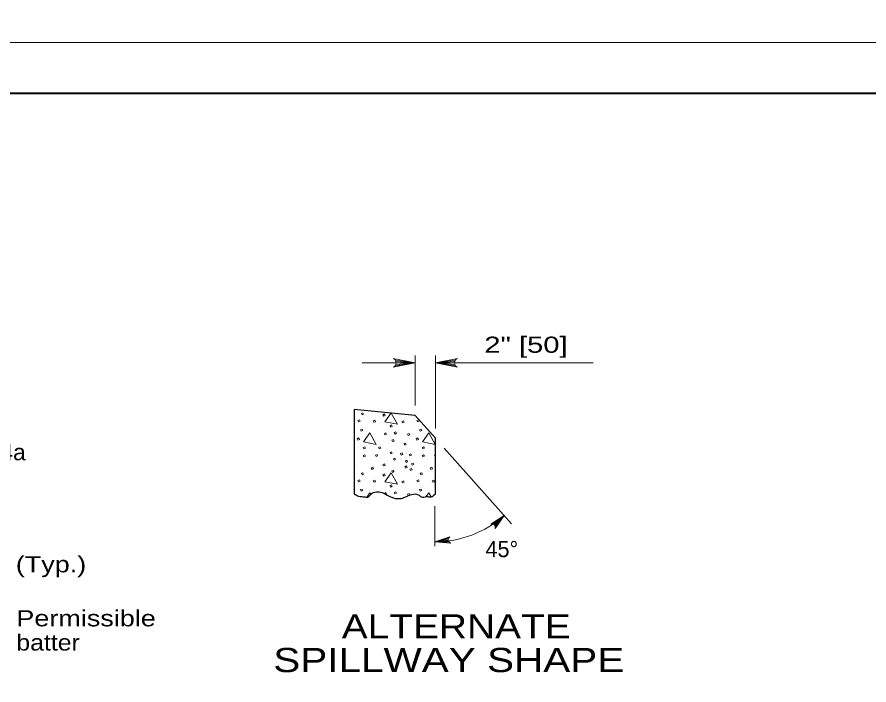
# Model space of a CAD drawing. Extents: x -1431.2 to -1397.2, y -1045.1 to -1001.1.
# Drawn here: x -1419.2 to -1410.82, y -1029.4 to -1022.83 of the extents above; entities that cross this region are included whole.
import ezdxf
from ezdxf.enums import TextEntityAlignment as Align

# ---------------------------------------------------------------- set-up
doc = ezdxf.new("R2010")
doc.units = 0
doc.header["$LTSCALE"] = 0.064
doc.linetypes.add('LONG_DASHED', pattern=[7.5, 6, -1.5])
doc.layers.add('1', color=7, linetype='Continuous', lineweight=13)
doc.layers.add('7', color=7, linetype='Continuous', lineweight=13)

msp = doc.modelspace()

# ---------------------------------------------------------------- linework, layer by layer
at = {"layer": '1', "lineweight": 25}
for p, q in [((-1429.24575, -1023.57983), (-1397.74575, -1023.57983)), ((-1415.08442, -1026.97317), (-1415.28442, -1026.74817)), ((-1415.08442, -1027.52167), (-1415.08442, -1026.97317))]:
    msp.add_line(p, q, dxfattribs=at)
at = {"layer": '1'}
for p, q in [((-1415.28442, -1026.65283), (-1415.28442, -1026.16033)), ((-1415.08442, -1026.87775), (-1415.08442, -1026.16033)), ((-1415.283, -1026.23167), (-1415.80542, -1026.23167)), ((-1415.481, -1026.26192), (-1415.283, -1026.23167)), ((-1415.47867, -1026.20433), (-1415.283, -1026.23167)), ((-1415.47358, -1026.23167), (-1415.283, -1026.23167)), ((-1415.4735, -1026.24925), (-1415.283, -1026.23167)), ((-1415.47208, -1026.21783), (-1415.283, -1026.23167)), ((-1415.47, -1026.23167), (-1415.283, -1026.23167)), ((-1414.88733, -1026.20433), (-1415.083, -1026.23167)), ((-1414.89392, -1026.21783), (-1415.083, -1026.23167)), ((-1413.53358, -1026.23167), (-1415.083, -1026.23167)), ((-1414.89592, -1026.23167), (-1415.083, -1026.23167)), ((-1414.8925, -1026.24925), (-1415.083, -1026.23167)), ((-1414.885, -1026.26192), (-1415.083, -1026.23167)), ((-1414.33558, -1027.81517), (-1414.997, -1027.07142)), ((-1415.88217, -1027.21875), (-1415.88375, -1027.21933)), ((-1415.75667, -1027.55067), (-1415.72858, -1027.51058)), ((-1415.72858, -1027.51058), (-1415.72058, -1027.525)), ((-1415.17508, -1027.548), (-1415.14883, -1027.51058)), ((-1415.14883, -1027.51058), (-1415.12708, -1027.5495)), ((-1415.08908, -1027.64242), (-1415.08908, -1028.03642)), ((-1414.52175, -1027.81608), (-1414.409, -1027.73458)), ((-1414.51183, -1027.82008), (-1414.409, -1027.73458)), ((-1414.50367, -1027.82617), (-1414.409, -1027.73458)), ((-1414.49717, -1027.83675), (-1414.409, -1027.73458)), ((-1414.495, -1027.8465), (-1414.409, -1027.73458)), ((-1414.9525, -1027.95417), (-1415.08892, -1027.991)), ((-1414.95642, -1027.96325), (-1415.08892, -1027.991)), ((-1414.9575, -1027.97633), (-1415.08892, -1027.991)), ((-1414.95517, -1027.98558), (-1415.08892, -1027.991)), ((-1414.9495, -1027.99458), (-1415.08892, -1027.991))]:
    msp.add_line(p, q, dxfattribs=at)
at = {"layer": '1', "linetype": 'LONG_DASHED'}
for points in [[(-1431.24575, -1023.07983), (-1397.24575, -1023.07983), (-1397.24575, -1001.07983), (-1431.24575, -1001.07983)], [(-1431.24575, -1045.07983), (-1397.24575, -1045.07983), (-1397.24575, -1023.07983), (-1431.24575, -1023.07983)]]:
    msp.add_lwpolyline(points, close=True, dxfattribs=at)
at = {"layer": '1', "lineweight": 40}
msp.add_lwpolyline([(-1429.24575, -1023.57983), (-1397.74575, -1023.57983), (-1397.74575, -1044.57983), (-1429.24575, -1044.57983)], close=True, dxfattribs=at)
at = {"layer": '1'}
for points in [[(-1415.49917, -1026.27492), (-1415.283, -1026.23167), (-1415.49917, -1026.1885)], [(-1414.86683, -1026.27492), (-1415.083, -1026.23167), (-1414.86683, -1026.1885)], [(-1415.51808, -1026.72542), (-1415.456, -1026.83633), (-1415.58108, -1026.81192), (-1415.52017, -1026.72508)], [(-1415.08442, -1027.13592), (-1415.09392, -1027.14042), (-1415.08783, -1027.15467), (-1415.08442, -1027.153)], [(-1415.88375, -1027.236), (-1415.87608, -1027.233), (-1415.88217, -1027.21875)], [(-1415.57092, -1027.50858), (-1415.58617, -1027.51567), (-1415.58417, -1027.52033)], [(-1415.57125, -1027.52633), (-1415.56483, -1027.52383), (-1415.57092, -1027.50858)], [(-1414.49742, -1027.86208), (-1414.409, -1027.73458), (-1414.54017, -1027.81808)], [(-1414.94058, -1027.9435), (-1415.08892, -1027.991), (-1414.93383, -1028.00425)]]:
    msp.add_lwpolyline(points, dxfattribs=at)
at = {"layer": '1', "lineweight": 25}
msp.add_lwpolyline([(-1415.28442, -1026.74817), (-1415.88375, -1026.68958), (-1415.88375, -1027.52167)], dxfattribs=at)
at = {"layer": '1'}
for points in [[(-1415.79675, -1026.7225), (-1415.812, -1026.72858), (-1415.80592, -1026.74283), (-1415.79058, -1026.73667)], [(-1415.58417, -1026.73467), (-1415.59942, -1026.74175), (-1415.59233, -1026.756), (-1415.57708, -1026.74992)], [(-1415.83133, -1026.79267), (-1415.84658, -1026.79875), (-1415.83942, -1026.813), (-1415.82417, -1026.80683)], [(-1415.67975, -1026.79667), (-1415.695, -1026.80283), (-1415.68892, -1026.817), (-1415.67367, -1026.81092)], [(-1415.39908, -1026.80283), (-1415.41433, -1026.80892), (-1415.40717, -1026.82317), (-1415.39192, -1026.817)], [(-1415.25158, -1026.79267), (-1415.26683, -1026.79875), (-1415.25975, -1026.813), (-1415.2445, -1026.80683)], [(-1415.80383, -1026.88317), (-1415.81908, -1026.88925), (-1415.813, -1026.9035), (-1415.79775, -1026.89742)], [(-1415.57092, -1026.91875), (-1415.58617, -1026.92583), (-1415.58008, -1026.94008), (-1415.56483, -1026.934)], [(-1415.515, -1026.8425), (-1415.53025, -1026.84858), (-1415.52417, -1026.86383), (-1415.50892, -1026.85667)], [(-1415.47333, -1026.91058), (-1415.48858, -1026.91667), (-1415.4825, -1026.93192), (-1415.46717, -1026.92483)], [(-1415.22417, -1026.88317), (-1415.23942, -1026.88925), (-1415.23325, -1026.9035), (-1415.218, -1026.89742)], [(-1415.83742, -1026.97058), (-1415.85267, -1026.97775), (-1415.84558, -1026.99192), (-1415.83025, -1026.98583)], [(-1415.72858, -1026.92075), (-1415.6655, -1027.03367), (-1415.79058, -1027.00925)], [(-1415.49667, -1026.98683), (-1415.51192, -1026.993), (-1415.50483, -1027.00717), (-1415.48958, -1027.00108)], [(-1415.34208, -1026.92583), (-1415.35733, -1026.933), (-1415.35125, -1026.94725), (-1415.336, -1026.94008)], [(-1415.25767, -1026.97058), (-1415.27292, -1026.97775), (-1415.26583, -1026.99192), (-1415.25058, -1026.98583)], [(-1415.14883, -1026.92075), (-1415.08583, -1027.03367), (-1415.21092, -1027.00925)], [(-1415.77942, -1027.057), (-1415.79467, -1027.06317), (-1415.78758, -1027.07733), (-1415.77233, -1027.07125)], [(-1415.62792, -1027.057), (-1415.64317, -1027.06417), (-1415.63708, -1027.07842), (-1415.62175, -1027.07225)], [(-1415.37667, -1027.02042), (-1415.39192, -1027.0265), (-1415.38583, -1027.04175), (-1415.37058, -1027.03467)], [(-1415.19975, -1027.057), (-1415.215, -1027.06317), (-1415.20783, -1027.07733), (-1415.19258, -1027.07125)], [(-1415.77942, -1027.13633), (-1415.79467, -1027.14242), (-1415.78758, -1027.15775), (-1415.77233, -1027.15058)], [(-1415.65842, -1027.13333), (-1415.67367, -1027.14042), (-1415.66758, -1027.15467), (-1415.65233, -1027.14758)], [(-1415.515, -1027.10583), (-1415.53025, -1027.113), (-1415.52317, -1027.12717), (-1415.50792, -1027.12008)], [(-1415.48142, -1027.16892), (-1415.49667, -1027.176), (-1415.49058, -1027.19025), (-1415.47533, -1027.18317)], [(-1415.41125, -1027.11808), (-1415.4265, -1027.12417), (-1415.41942, -1027.13942), (-1415.40417, -1027.13225)], [(-1415.32483, -1027.12617), (-1415.34008, -1027.13333), (-1415.334, -1027.14758), (-1415.31875, -1027.14142)], [(-1415.19975, -1027.13633), (-1415.215, -1027.14242), (-1415.20783, -1027.15775), (-1415.19258, -1027.15058)], [(-1415.58517, -1027.22483), (-1415.60042, -1027.23192), (-1415.59433, -1027.24617), (-1415.57908, -1027.24008)], [(-1415.36858, -1027.24617), (-1415.38383, -1027.25333), (-1415.37767, -1027.26758), (-1415.36242, -1027.26042)], [(-1415.3635, -1027.19025), (-1415.37875, -1027.19742), (-1415.37258, -1027.21158), (-1415.35733, -1027.2055)], [(-1415.30242, -1027.21875), (-1415.31767, -1027.22483), (-1415.31158, -1027.23908), (-1415.29633, -1027.233)], [(-1415.79675, -1027.31225), (-1415.812, -1027.31842), (-1415.80592, -1027.33267), (-1415.79058, -1027.3265)], [(-1415.69908, -1027.25942), (-1415.71433, -1027.2655), (-1415.70725, -1027.28075), (-1415.692, -1027.27367)], [(-1415.58417, -1027.3245), (-1415.59942, -1027.33158), (-1415.59233, -1027.34583), (-1415.57708, -1027.33975)], [(-1415.51908, -1027.31333), (-1415.456, -1027.42617), (-1415.58108, -1027.40175)], [(-1415.49775, -1027.28792), (-1415.513, -1027.294), (-1415.50683, -1027.30925), (-1415.49158, -1027.30208)], [(-1415.31875, -1027.26958), (-1415.334, -1027.27667), (-1415.32783, -1027.29092), (-1415.31258, -1027.28383)], [(-1415.217, -1027.31225), (-1415.23225, -1027.31842), (-1415.22617, -1027.33267), (-1415.21092, -1027.3265)], [(-1415.11942, -1027.25942), (-1415.13467, -1027.2655), (-1415.1275, -1027.28075), (-1415.11225, -1027.27367)], [(-1415.83133, -1027.38242), (-1415.84658, -1027.38858), (-1415.83942, -1027.40283), (-1415.82417, -1027.39667)], [(-1415.67975, -1027.3865), (-1415.695, -1027.39258), (-1415.68892, -1027.40683), (-1415.67367, -1027.40075)], [(-1415.39908, -1027.39258), (-1415.41433, -1027.39875), (-1415.40717, -1027.413), (-1415.39192, -1027.40683)], [(-1415.25158, -1027.38242), (-1415.26683, -1027.38858), (-1415.25975, -1027.40283), (-1415.2445, -1027.39667)], [(-1415.10008, -1027.3865), (-1415.11533, -1027.39258), (-1415.10917, -1027.40683), (-1415.09392, -1027.40075)], [(-1415.80383, -1027.473), (-1415.81908, -1027.47908), (-1415.813, -1027.49333), (-1415.79775, -1027.48717)], [(-1415.515, -1027.43225), (-1415.53025, -1027.43842), (-1415.52417, -1027.45367), (-1415.50892, -1027.4465)], [(-1415.47333, -1027.50042), (-1415.48858, -1027.5065), (-1415.4825, -1027.52175), (-1415.46717, -1027.51467)], [(-1415.22417, -1027.473), (-1415.23942, -1027.47908), (-1415.23325, -1027.49333), (-1415.218, -1027.48717)], [(-1415.34208, -1027.51567), (-1415.35733, -1027.52275), (-1415.35125, -1027.537), (-1415.336, -1027.52992)]]:
    msp.add_lwpolyline(points, close=True, dxfattribs=at)
for centre, radius, start, end in [((-1415.51659, -1026.23165), 0.04665, 292.08605, 67.91218), ((-1414.84939, -1026.23165), 0.04665, 112.08782, 247.91395), ((-1415.08439, -1026.97314), 1.01787, 269.74586, 311.57234)]:
    msp.add_arc(centre, radius, start, end, dxfattribs=at)
for centre, start_param, end_param in [((-1414.52772, -1027.8488), 2.7228806, 5.0934937), ((-1414.92495, -1027.97248), 5.2104535, 7.5810666)]:
    msp.add_ellipse(centre, major_axis=(-0.03293, 0), ratio=0.999895, start_param=start_param, end_param=end_param, dxfattribs=at)
at = {"layer": '1', "lineweight": 25}
msp.add_spline([(-1415.88375, -1027.52167), (-1415.83758, -1027.54292), (-1415.77708, -1027.55108), (-1415.742, -1027.55033), (-1415.71717, -1027.52108), (-1415.66442, -1027.50167), (-1415.61233, -1027.50725), (-1415.5635, -1027.53), (-1415.51358, -1027.55408), (-1415.47825, -1027.56517), (-1415.4335, -1027.567), (-1415.38417, -1027.553), (-1415.31467, -1027.52542), (-1415.25292, -1027.5295), (-1415.22233, -1027.55133), (-1415.17042, -1027.54767), (-1415.12692, -1027.5495), (-1415.08442, -1027.52167)], degree=3, dxfattribs=at)

# ---------------------------------------------------------------- texts
at = {"layer": '1', "width": 1.35}
msp.add_text('2" [50]', height=0.1588, dxfattribs=at).set_placement((-1414.19338, -1026.13275), align=Align.CENTER)
at = {"layer": '1'}
for s, height, width, p in [('M4a', 0.1588, 1.05, (-1419.54725, -1027.18992)), ('M5b (Typ.)', 0.1588, 1.25, (-1419.80133, -1028.29267)), ('ALTERNATE', 0.2382, 1.2, (-1416.005, -1028.94283)), ('SPILLWAY SHAPE', 0.2382, 1.25, (-1416.67858, -1029.27433))]:
    msp.add_text(s, height=height, dxfattribs=dict(at, width=width)).set_placement(p)
msp.add_text('45°', height=0.1588, dxfattribs=at).set_placement((-1414.43054, -1028.14325), align=Align.CENTER)
at = {"layer": '7'}
for s, width, p in [('Permissible', 1.25, (-1419.20567, -1028.82392)), ('batter', 1.15, (-1419.20567, -1029.06208))]:
    msp.add_text(s, height=0.1588, dxfattribs=dict(at, width=width)).set_placement(p)

doc.saveas('drawing.dxf')
